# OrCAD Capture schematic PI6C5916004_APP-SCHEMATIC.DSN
size B; title: PI6C5916004 Application Schematic; rev: 1.0; note: Diodes Inc. Clock IC Application Engineering
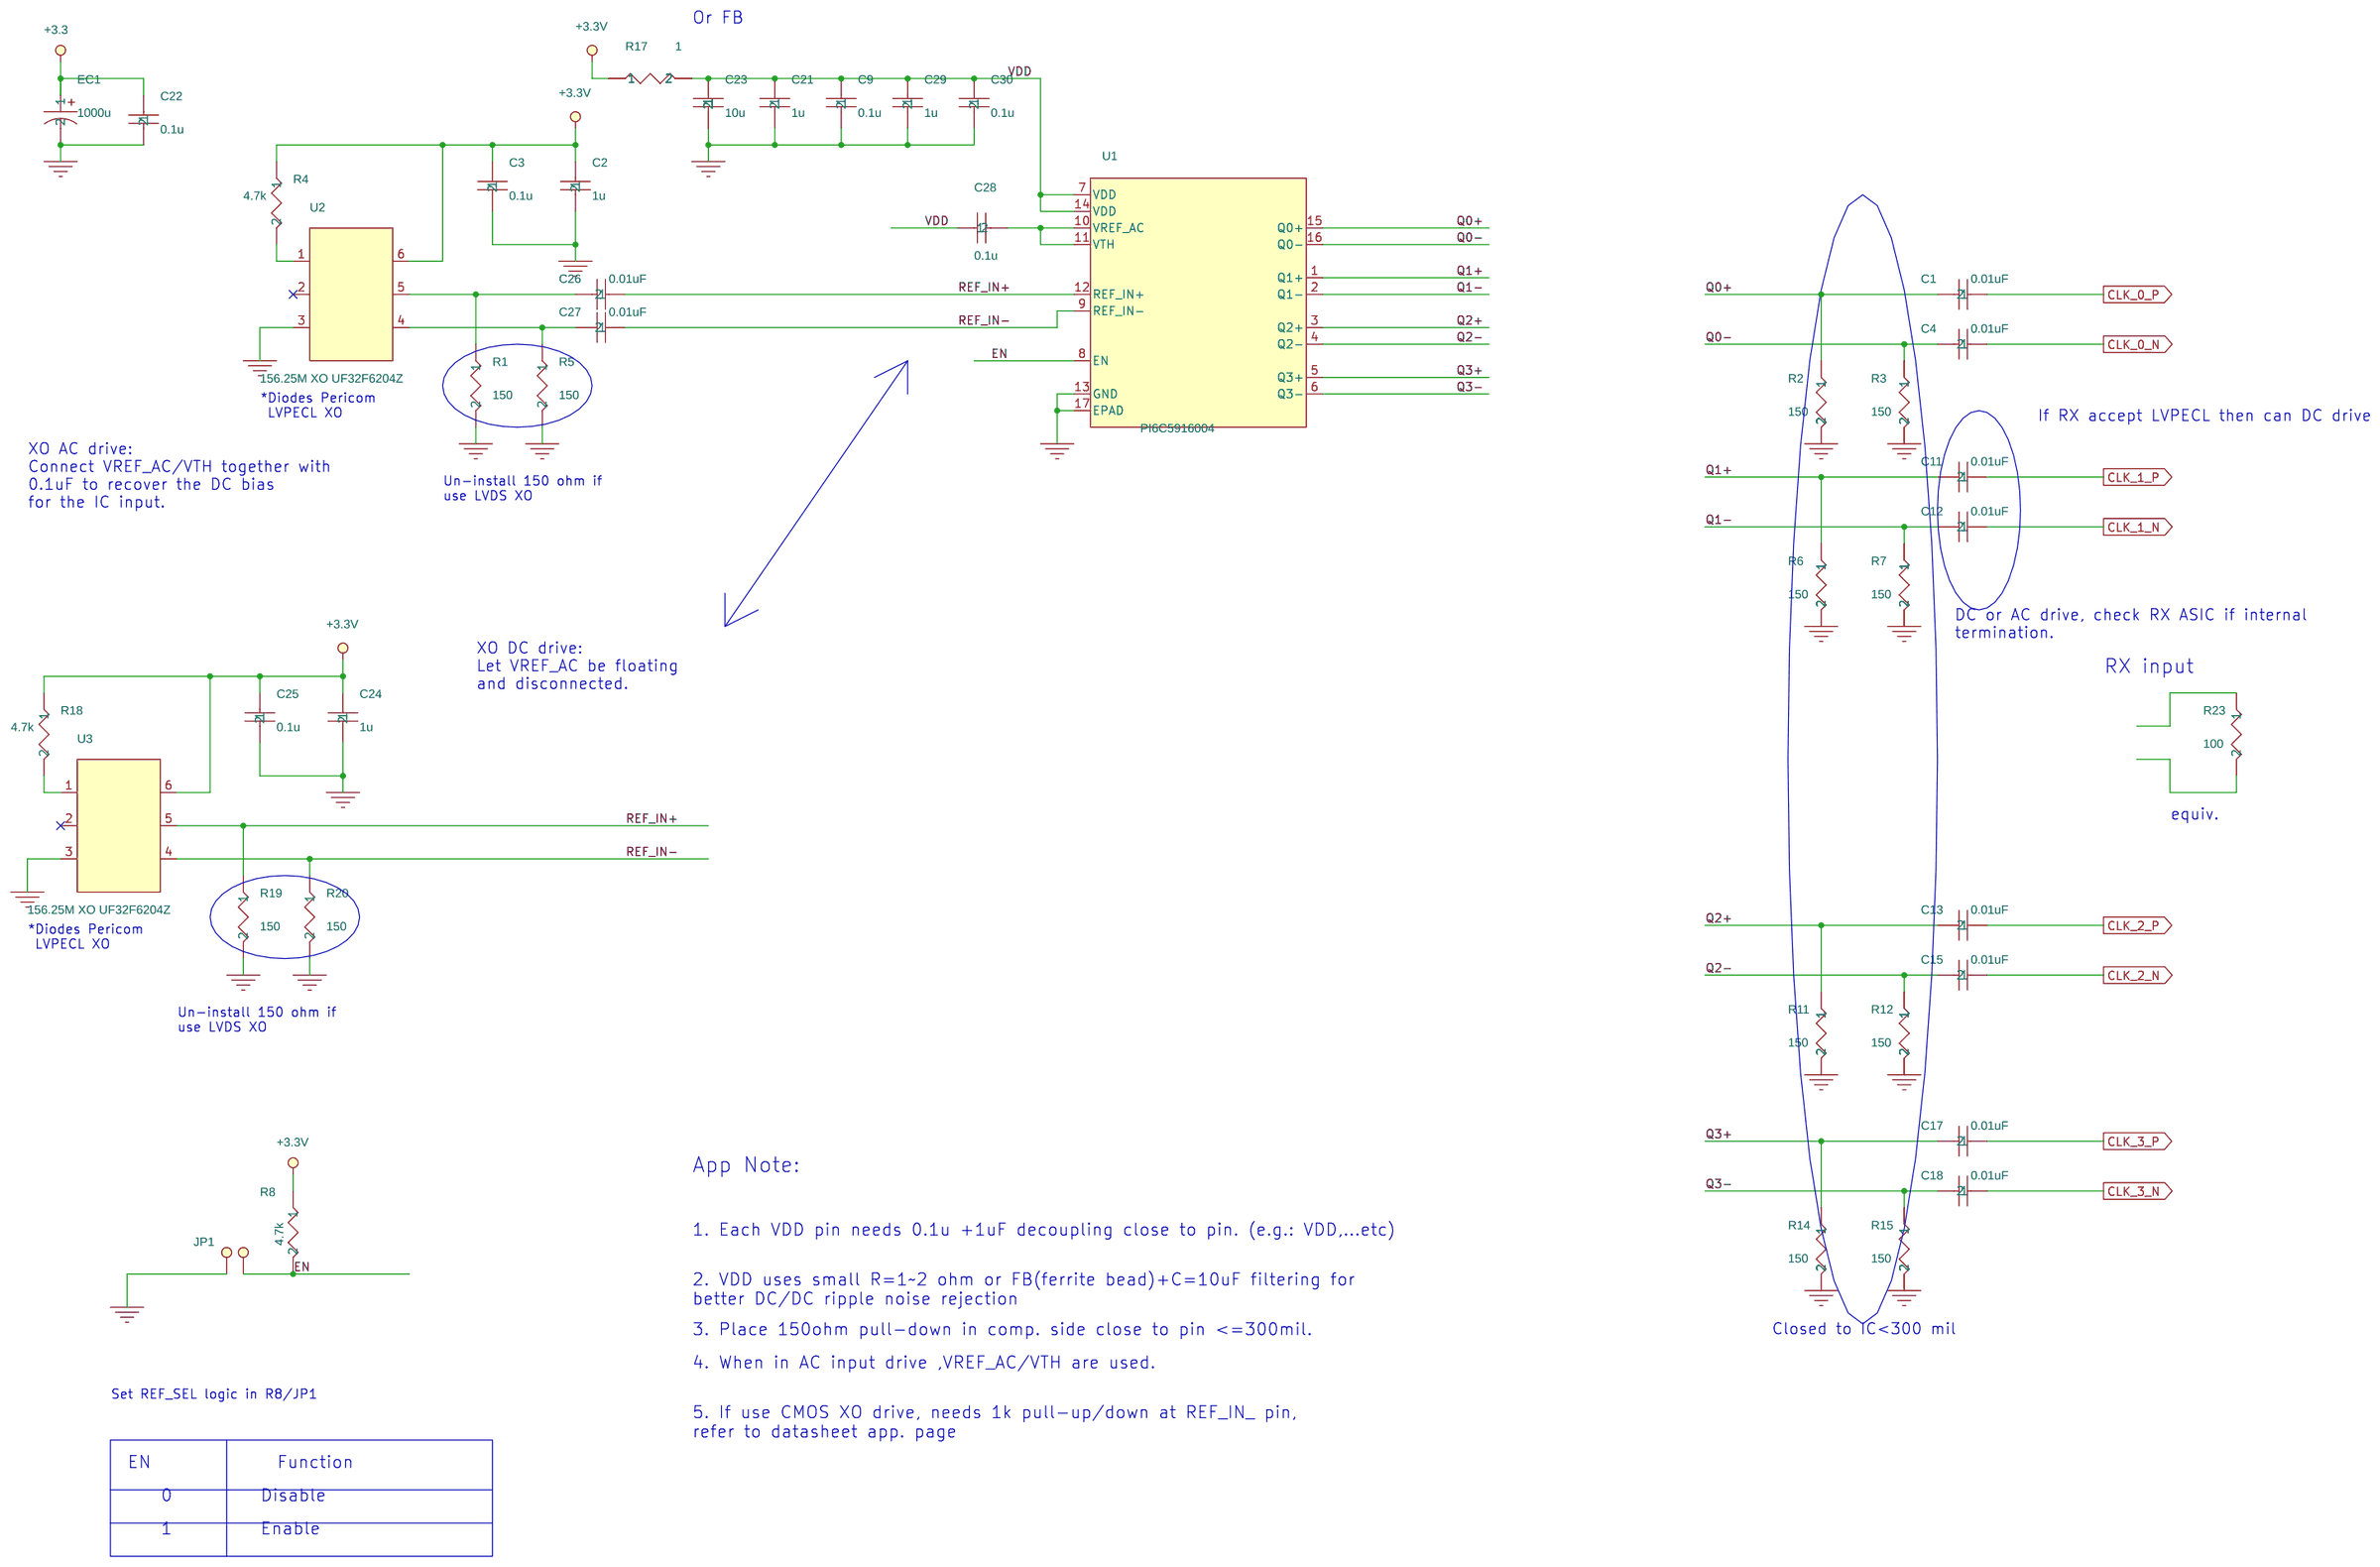
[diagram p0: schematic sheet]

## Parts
C1  0.01uF  [CC_0402]
C2  1u  [CC_0402]
C3  0.1u  [CC_0402]
C4  0.01uF  [CC_0402]
C9  0.1u  [CC_0402]
C11  0.01uF  [CC_0402]
C12  0.01uF  [CC_0402]
C13  0.01uF  [CC_0402]
C15  0.01uF  [CC_0402]
C17  0.01uF  [CC_0402]
C18  0.01uF  [CC_0402]
C21  1u  [CC_0805]
C22  0.1u  [CC_0402]
C23  10u  [CC_0805]
C24  1u  [CC_0402]
C25  0.1u  [CC_0402]
C26  0.01uF  [CC_0402]
C27  0.01uF  [CC_0402]
C28  0.1u  [CC_0402]
C29  1u  [CC_0805]
C30  0.1u  [CC_0402]
EC1  1000u  [CAP1000UF]
JP1  2x1 Pin Header  [2x1 Pin Header]
R1  150  [R_0402]
R2  150  [R_0402]
R3  150  [R_0402]
R4  4.7k  [R_0402]
R5  150  [R_0402]
R6  150  [R_0402]
R7  150  [R_0402]
R8  4.7k  [R_0402]
R11  150  [R_0402]
R12  150  [R_0402]
R14  150  [R_0402]
R15  150  [R_0402]
R17  1  [R_0402]
R18  4.7k  [R_0402]
R19  150  [R_0402]
R20  150  [R_0402]
R23  100  [R_0402]
U1  PI6C5916004
U2  156.25M XO UF32F6204Z  [XO 5X7]
U3  156.25M XO UF32F6204Z  [XO 5X7]

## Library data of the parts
C1 = C_10n_0402_2
C2 = C_0.1u_0402_5
C3 = C_0.1u_0402_4
C4 = C_10n_0402_7
C9 = C_0.1u_0402_3
C11 = C_10n_0402_6
C12 = C_10n_0402_9
C13 = C_10n_0402_8
C15 = C_10n_0402_1
C17 = C_10n_0402_5
C18 = C_10n_0402_4
C21 = C_1.0u_0805_2
C22 = C_0.1u_0402_2
C23 = C_1.0u_0805_1
C24 = C_0.1u_0402_7
C25 = C_0.1u_0402_6
C26 = C_10n_0402_3
C27 = C_10n_0402
C28 = C_0.1u_0402_1
C29 = C_1.0u_0805
C30 = C_0.1u_0402
EC1 = C_alum_1000u
JP1 = 2x1_Pin_Header
R1 = R_0402_7
R2 = R_0_7
R3 = R_0_3
R4 = R_0402_1
R5 = R_0402_5
R6 = R_0_6
R7 = R_0_2
R8 = R_0402
R11 = R_0
R12 = R_0_8
R14 = R_0_5
R15 = R_0_4
R17 = R_0402_4
R18 = R_0402_6
R19 = R_0402_3
R20 = R_0402_2
R23 = R_0_1
U1 = PI6C4911504-03_5
U2 U3 = XO_5X7

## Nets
+3.3V: C2.1 C3.1 C24.1 C25.1 R4.1 R8.1 R17.1 R18.1 U2.6 U3.6
GND: C2.2 C3.2 C9.2 C21.2 C22.2 C23.2 C24.2 C25.2 C29.2 C30.2 EC1.2 JP1.1 R1.2 R2.2 R3.2 R5.2 R6.2 R7.2 R11.2 R12.2 R14.2 R15.2 R19.2 R20.2 U1.13(GND) U1.17(EPAD) U2.3 U3.3
VDD: C9.1 C21.1 C23.1 C28.1 C29.1 C30.1 R17.2 U1.7(VDD) U1.14(VDD)
+3.3: C22.1 EC1.1
CLK_0_N: C4.1
CLK_0_P: C1.1
CLK_1_N: C12.1
CLK_1_P: C11.1
CLK_2_N: C15.1
CLK_2_P: C13.1
CLK_3_N: C18.1
CLK_3_P: C17.1
EN: JP1.2 R8.2 U1.8(EN)
Q0+: C1.2 R2.1 U1.15(Q0+)
Q0-: C4.2 R3.1 U1.16(Q0-)
Q1+: C11.2 R6.1 U1.1(Q1+)
Q1-: C12.2 R7.1 U1.2(Q1-)
Q2+: C13.2 R11.1 U1.3(Q2+)
Q2-: C15.2 R12.1 U1.4(Q2-)
Q3+: C17.2 R14.1 U1.5(Q3+)
Q3-: C18.2 R15.1 U1.6(Q3-)
REF_IN+: C26.1 R19.1 U1.12(REF_IN+) U3.5
REF_IN-: C27.1 R20.1 U1.9(REF_IN-) U3.4
N4608779: C27.2 R5.1 U2.4
N4608783: C26.2 R1.1 U2.5
N4608823: R4.2 U2.1
N4609914: R18.2 U3.1
N4639870: C28.2 U1.10(VREF_AC) U1.11(VTH)

Not connected (* = marked no-connect by the designer): R23 1 2; U2 2*; U3 2*

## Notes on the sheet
- Or FB
- *Diodes Pericom
   LVPECL XO
- If RX accept LVPECL then can DC drive
- XO AC drive:
  Connect VREF_AC/VTH together with
  0.1uF to recover the DC bias
  for the IC input.
- Un-install 150 ohm if
  use LVDS XO
- DC or AC drive, check RX ASIC if internal
  termination.
- XO DC drive:
  Let VREF_AC be floating
  and disconnected.
- RX input
- equiv.
- *Diodes Pericom
   LVPECL XO
- Un-install 150 ohm if
  use LVDS XO
- App Note:
- 1. Each VDD pin needs 0.1u +1uF decoupling close to pin. (e.g.: VDD,...etc)
- 2. VDD uses small R=1~2 ohm or FB(ferrite bead)+C=10uF filtering for
  better DC/DC ripple noise rejection
- 3. Place 150ohm pull-down in comp. side close to pin <=300mil.
- Closed to IC<300 mil
- 4. When in AC input drive ,VREF_AC/VTH are used.
- Set REF_SEL logic in R8/JP1
- 5. If use CMOS XO drive, needs 1k pull-up/down at REF_IN_ pin,
  refer to datasheet app. page
- EN
- Function
- 0
- Disable
- 1
- Enable
